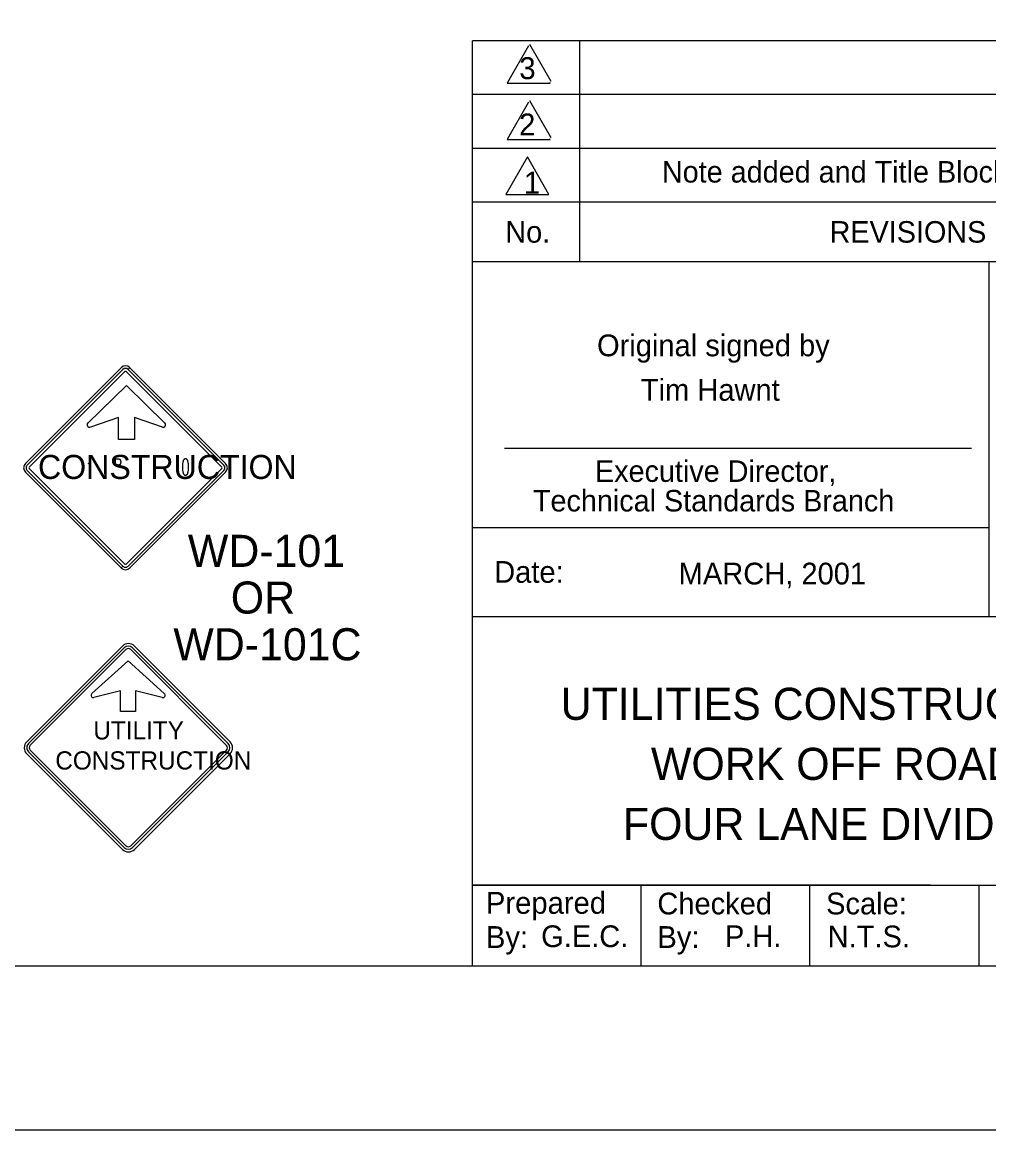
# Model space of a CAD drawing. Extents: x 1351 to 1567, y 178 to 457.
# Drawn here: x 1454.7 to 1518.5, y 177.9 to 251 of the extents above; entities that cross this region are included whole.
import ezdxf

# ---------------------------------------------------------------- set-up
doc = ezdxf.new("R2010")
doc.units = 0
for name, color, linetype in [('Level 1', 7, 'Continuous'), ('Level 10', 7, 'Continuous'), ('Level 60', 7, 'Continuous')]:
    doc.layers.add(name, color=color, linetype=linetype)

msp = doc.modelspace()

# ---------------------------------------------------------------- linework, layer by layer
at = {"layer": 'Level 1'}
for p, q in [((1454.953, 221.873), (1461.263, 228.183)), ((1455.068, 221.758), (1461.378, 228.068)), ((1455.206, 221.62), (1461.516, 227.93)), ((1461.594, 227.93), (1467.905, 221.62)), ((1461.847, 228.183), (1461.732, 228.068)), ((1461.732, 228.068), (1468.042, 221.758)), ((1461.732, 228.068), (1461.732, 228.068)), ((1461.847, 228.183), (1468.157, 221.873)), ((1459.07, 224.537), (1461.611, 227.012)), ((1461.612, 227.012), (1464.153, 224.537)), ((1461.085, 224.907), (1459.236, 224.268)), ((1461.085, 223.45), (1461.085, 224.907)), ((1463.987, 224.268), (1462.138, 224.907)), ((1462.138, 224.907), (1462.138, 223.45)), ((1462.138, 223.45), (1461.085, 223.45)), ((1461.114, 222.145), (1461.125, 222.145)), ((1461.114, 222.145), (1461.125, 222.145)), ((1461.378, 215.094), (1455.068, 221.404)), ((1461.516, 215.232), (1455.206, 221.542)), ((1467.905, 221.542), (1461.594, 215.232)), ((1468.042, 221.404), (1461.732, 215.094)), ((1461.263, 214.979), (1454.953, 221.289)), ((1468.157, 221.289), (1461.847, 214.979)), ((1461.378, 215.094), (1461.263, 214.979)), ((1461.263, 214.98), (1461.263, 214.979)), ((1461.378, 215.095), (1461.378, 215.094)), ((1461.531, 215.247), (1461.516, 215.232)), ((1459.47, 206.433), (1459.47, 206.433)), ((1459.47, 206.433), (1459.47, 206.433)), ((1459.47, 206.433), (1459.47, 206.433))]:
    msp.add_line(p, q, dxfattribs=at)
for points in [[(1461.125, 222.145), (1460.878, 222.145), (1460.878, 221.785), (1461.125, 221.785)], [(1461.125, 222.145), (1460.878, 222.145), (1460.878, 221.785), (1461.125, 221.785)], [(1461.114, 221.785), (1461.125, 221.785), (1461.137, 221.796), (1461.148, 221.796), (1461.159, 221.796), (1461.171, 221.796), (1461.171, 221.807), (1461.182, 221.807), (1461.193, 221.807), (1461.204, 221.819), (1461.216, 221.83), (1461.227, 221.841), (1461.238, 221.852), (1461.238, 221.864), (1461.238, 221.875), (1461.249, 221.897), (1461.249, 221.909), (1461.249, 221.92), (1461.249, 221.942), (1461.261, 221.954), (1461.261, 221.965), (1461.261, 221.987), (1461.249, 221.999), (1461.249, 222.01), (1461.249, 222.032), (1461.249, 222.044), (1461.238, 222.055), (1461.238, 222.078), (1461.227, 222.089), (1461.227, 222.1), (1461.216, 222.111), (1461.204, 222.111), (1461.204, 222.123), (1461.193, 222.123), (1461.182, 222.134), (1461.171, 222.134), (1461.159, 222.134), (1461.148, 222.145), (1461.137, 222.145), (1461.125, 222.145), (1461.114, 222.145)], [(1461.114, 221.785), (1461.125, 221.785), (1461.137, 221.796), (1461.148, 221.796), (1461.159, 221.796), (1461.171, 221.796), (1461.171, 221.807), (1461.182, 221.807), (1461.193, 221.807), (1461.204, 221.819), (1461.216, 221.83), (1461.227, 221.841), (1461.238, 221.852), (1461.238, 221.864), (1461.238, 221.875), (1461.249, 221.897), (1461.249, 221.909), (1461.249, 221.92), (1461.249, 221.942), (1461.261, 221.954), (1461.261, 221.965), (1461.261, 221.987), (1461.249, 221.999), (1461.249, 222.01), (1461.249, 222.032), (1461.249, 222.044), (1461.238, 222.055), (1461.238, 222.078), (1461.227, 222.089), (1461.227, 222.1), (1461.216, 222.111), (1461.204, 222.111), (1461.204, 222.123), (1461.193, 222.123), (1461.182, 222.134), (1461.171, 222.134), (1461.159, 222.134), (1461.148, 222.145), (1461.137, 222.145), (1461.125, 222.145), (1461.114, 222.145)], [(1465.36, 221.199), (1465.371, 221.188), (1465.371, 221.177), (1465.382, 221.165), (1465.394, 221.154), (1465.394, 221.143), (1465.405, 221.132), (1465.416, 221.132), (1465.427, 221.12), (1465.439, 221.12), (1465.439, 221.109), (1465.45, 221.109), (1465.461, 221.109), (1465.473, 221.098), (1465.484, 221.098), (1465.495, 221.098), (1465.506, 221.098), (1465.518, 221.098), (1465.529, 221.098), (1465.54, 221.098), (1465.551, 221.098), (1465.563, 221.109), (1465.574, 221.109), (1465.585, 221.109), (1465.596, 221.12), (1465.608, 221.132), (1465.619, 221.143), (1465.63, 221.143), (1465.63, 221.154), (1465.641, 221.165), (1465.653, 221.177), (1465.664, 221.188), (1465.664, 221.199), (1465.675, 221.233), (1465.675, 221.267), (1465.686, 221.301), (1465.698, 221.334), (1465.698, 221.368), (1465.709, 221.402), (1465.709, 221.447), (1465.72, 221.481), (1465.72, 221.515), (1465.72, 221.548), (1465.72, 221.582), (1465.72, 221.616), (1465.72, 221.65), (1465.72, 221.683), (1465.72, 221.717), (1465.72, 221.751), (1465.709, 221.796), (1465.709, 221.83), (1465.709, 221.864), (1465.698, 221.897), (1465.698, 221.931), (1465.686, 221.965), (1465.675, 221.999), (1465.675, 222.032), (1465.664, 222.066), (1465.653, 222.078), (1465.653, 222.089), (1465.641, 222.1), (1465.63, 222.111), (1465.63, 222.123), (1465.619, 222.134), (1465.608, 222.134), (1465.596, 222.145), (1465.585, 222.156), (1465.574, 222.156), (1465.563, 222.156), (1465.551, 222.168), (1465.54, 222.168), (1465.529, 222.168), (1465.518, 222.168), (1465.506, 222.168), (1465.495, 222.168), (1465.484, 222.168), (1465.473, 222.168), (1465.461, 222.168), (1465.45, 222.156), (1465.439, 222.156), (1465.439, 222.145), (1465.427, 222.145), (1465.416, 222.134), (1465.405, 222.134), (1465.405, 222.123), (1465.394, 222.111), (1465.382, 222.111), (1465.382, 222.1), (1465.371, 222.089), (1465.371, 222.078), (1465.36, 222.066), (1465.36, 222.055), (1465.36, 222.044), (1465.36, 222.032), (1465.349, 221.999), (1465.337, 221.976), (1465.337, 221.942), (1465.326, 221.909), (1465.315, 221.875), (1465.315, 221.841), (1465.315, 221.807)], [(1465.36, 221.199), (1465.371, 221.188), (1465.371, 221.177), (1465.382, 221.165), (1465.394, 221.154), (1465.394, 221.143), (1465.405, 221.132), (1465.416, 221.132), (1465.427, 221.12), (1465.439, 221.12), (1465.439, 221.109), (1465.45, 221.109), (1465.461, 221.109), (1465.473, 221.098), (1465.484, 221.098), (1465.495, 221.098), (1465.506, 221.098), (1465.518, 221.098), (1465.529, 221.098), (1465.54, 221.098), (1465.551, 221.098), (1465.563, 221.109), (1465.574, 221.109), (1465.585, 221.109), (1465.596, 221.12), (1465.608, 221.132), (1465.619, 221.143), (1465.63, 221.143), (1465.63, 221.154), (1465.641, 221.165), (1465.653, 221.177), (1465.664, 221.188), (1465.664, 221.199), (1465.675, 221.233), (1465.675, 221.267), (1465.686, 221.301), (1465.698, 221.334), (1465.698, 221.368), (1465.709, 221.402), (1465.709, 221.447), (1465.72, 221.481), (1465.72, 221.515), (1465.72, 221.548), (1465.72, 221.582), (1465.72, 221.616), (1465.72, 221.65), (1465.72, 221.683), (1465.72, 221.717), (1465.72, 221.751), (1465.709, 221.796), (1465.709, 221.83), (1465.709, 221.864), (1465.698, 221.897), (1465.698, 221.931), (1465.686, 221.965), (1465.675, 221.999), (1465.675, 222.032), (1465.664, 222.066), (1465.653, 222.078), (1465.653, 222.089), (1465.641, 222.1), (1465.63, 222.111), (1465.63, 222.123), (1465.619, 222.134), (1465.608, 222.134), (1465.596, 222.145), (1465.585, 222.156), (1465.574, 222.156), (1465.563, 222.156), (1465.551, 222.168), (1465.54, 222.168), (1465.529, 222.168), (1465.518, 222.168), (1465.506, 222.168), (1465.495, 222.168), (1465.484, 222.168), (1465.473, 222.168), (1465.461, 222.168), (1465.45, 222.156), (1465.439, 222.156), (1465.439, 222.145), (1465.427, 222.145), (1465.416, 222.134), (1465.405, 222.134), (1465.405, 222.123), (1465.394, 222.111), (1465.382, 222.111), (1465.382, 222.1), (1465.371, 222.089), (1465.371, 222.078), (1465.36, 222.066), (1465.36, 222.055), (1465.36, 222.044), (1465.36, 222.032), (1465.349, 221.999), (1465.337, 221.976), (1465.337, 221.942), (1465.326, 221.909), (1465.315, 221.875), (1465.315, 221.841), (1465.315, 221.807)], [(1459.245, 221.785), (1459.087, 221.875)], [(1465.315, 221.807), (1465.304, 221.774), (1465.304, 221.74), (1465.304, 221.706), (1465.304, 221.672), (1465.304, 221.638), (1465.304, 221.605), (1465.304, 221.571), (1465.304, 221.537), (1465.304, 221.503), (1465.315, 221.469), (1465.315, 221.436), (1465.315, 221.402), (1465.326, 221.368), (1465.326, 221.334), (1465.337, 221.301), (1465.349, 221.267), (1465.349, 221.233), (1465.36, 221.199)], [(1465.315, 221.807), (1465.304, 221.774), (1465.304, 221.74), (1465.304, 221.706), (1465.304, 221.672), (1465.304, 221.638), (1465.304, 221.605), (1465.304, 221.571), (1465.304, 221.537), (1465.304, 221.503), (1465.315, 221.469), (1465.315, 221.436), (1465.315, 221.402), (1465.326, 221.368), (1465.326, 221.334), (1465.337, 221.301), (1465.349, 221.267), (1465.349, 221.233), (1465.36, 221.199)], [(1455.04, 203.519), (1461.351, 209.829)], [(1455.158, 203.401), (1461.469, 209.711)], [(1462.02, 209.711), (1468.332, 203.398)], [(1462.139, 209.828), (1468.451, 203.516)], [(1455.277, 203.282), (1461.588, 209.592)], [(1461.903, 209.592), (1468.214, 203.279)], [(1459.336, 206.688), (1461.724, 208.862), (1464.115, 206.688)], [(1459.336, 206.688), (1461.724, 208.862), (1464.115, 206.688)], [(1459.336, 206.688), (1461.724, 208.862), (1464.115, 206.688)], [(1463.977, 206.433), (1462.221, 206.885), (1462.221, 205.516), (1461.232, 205.516), (1461.232, 206.885), (1459.47, 206.433)], [(1463.977, 206.433), (1462.221, 206.885), (1462.221, 205.516), (1461.232, 205.516), (1461.232, 206.885), (1459.47, 206.433)], [(1463.977, 206.433), (1462.221, 206.885), (1462.221, 205.516), (1461.232, 205.516), (1461.232, 206.885), (1459.47, 206.433)], [(1461.351, 196.418), (1455.04, 202.729)], [(1461.469, 196.537), (1455.158, 202.848)], [(1461.588, 196.654), (1455.277, 202.966)], [(1468.214, 202.964), (1461.903, 196.654)], [(1468.332, 202.846), (1462.021, 196.537)], [(1468.451, 202.728), (1462.139, 196.418)]]:
    msp.add_lwpolyline(points, dxfattribs=at)
for centre, radius, start, end in [((1461.555, 227.892), 0.413, 45.00012, 135), ((1461.555, 227.892), 0.25, 45.00012, 135), ((1461.555, 227.892), 0.0552, 44.99999, 135), ((1459.183, 224.422), 0.162, 134.244, 289.06341), ((1464.04, 224.422), 0.162, 250.93659, 45.756), ((1455.245, 221.581), 0.413, 135, 225), ((1455.245, 221.581), 0.25, 135, 225.00066), ((1455.245, 221.581), 0.0552, 135, 225), ((1467.865, 221.581), 0.0552, 315.00001, 44.99827), ((1467.865, 221.581), 0.25, 315, 45), ((1467.865, 221.581), 0.413, 315, 45), ((1461.555, 215.271), 0.413, 225, 315), ((1461.555, 215.271), 0.25, 224.99953, 315.00034), ((1461.555, 215.271), 0.0553, 225, 315.00069), ((1461.745, 209.433), 0.558, 44.99496, 134.99496), ((1461.745, 209.433), 0.558, 44.99496, 134.99496), ((1461.745, 209.433), 0.39, 44.99496, 134.99496), ((1461.745, 209.433), 0.223, 44.99496, 134.99496), ((1459.437, 206.577), 0.15, 132.30479, 284.40748), ((1459.437, 206.577), 0.15, 132.30479, 284.40748), ((1459.437, 206.577), 0.15, 132.30479, 284.40748), ((1464.015, 206.577), 0.15, 255.59252, 47.69521), ((1464.015, 206.577), 0.15, 255.59252, 47.69521), ((1464.015, 206.577), 0.15, 255.59252, 47.69521), ((1455.435, 203.124), 0.558, 134.99495, 224.99495), ((1455.435, 203.124), 0.39, 134.99495, 224.99495), ((1455.435, 203.124), 0.223, 134.99495, 224.99495), ((1468.056, 203.121), 0.223, 314.99496, 44.99495), ((1468.056, 203.121), 0.39, 314.99496, 44.99495), ((1468.056, 203.121), 0.558, 314.99496, 44.99495), ((1461.746, 196.812), 0.39, 224.99496, 314.99495), ((1461.746, 196.812), 0.223, 224.99496, 314.99495), ((1461.746, 196.812), 0.558, 224.99496, 314.99495)]:
    msp.add_arc(centre, radius, start, end, dxfattribs=at)
at = {"layer": 'Level 60'}
for p, q in [((1548.312, 249.746), (1484.432, 249.746)), ((1548.312, 249.746), (1484.432, 249.746)), ((1484.439, 243.274), (1484.439, 249.746)), ((1484.439, 243.274), (1484.439, 249.746)), ((1491.529, 243.274), (1491.529, 249.746)), ((1491.529, 243.274), (1491.529, 249.746)), ((1548.312, 246.197), (1484.432, 246.197)), ((1548.312, 246.197), (1484.432, 246.197)), ((1484.439, 235.196), (1484.439, 243.274)), ((1484.439, 235.196), (1484.439, 243.274)), ((1491.529, 235.196), (1491.529, 243.274)), ((1491.529, 235.196), (1491.529, 243.274)), ((1548.312, 242.648), (1484.432, 242.648)), ((1548.312, 242.648), (1484.432, 242.648)), ((1548.312, 239.1), (1484.432, 239.1)), ((1548.312, 239.1), (1484.432, 239.1)), ((1484.439, 188.732), (1484.439, 235.196)), ((1484.439, 235.196), (1548.312, 235.196)), ((1484.439, 235.196), (1548.312, 235.196)), ((1518.489, 235.196), (1518.489, 211.787)), ((1518.489, 235.196), (1518.489, 235.196)), ((1486.547, 222.882), (1517.348, 222.882)), ((1484.439, 217.639), (1518.489, 217.639)), ((1484.439, 211.787), (1548.282, 211.787)), ((1484.439, 194.053), (1548.282, 194.053)), ((1514.639, 194.053), (1484.439, 194.053)), ((1495.57, 188.732), (1495.57, 194.053)), ((1506.7, 188.732), (1506.7, 194.053)), ((1517.829, 194.053), (1517.829, 188.732)), ((1499.902, 188.732), (1499.902, 188.732))]:
    msp.add_line(p, q, dxfattribs=at)
for points in [[(1567.408, 456.923), (1351.408, 456.923), (1351.408, 177.923), (1567.408, 177.923)], [(1548.282, 446.114), (1361.408, 446.114), (1361.408, 188.732), (1548.282, 188.732)], [(1488.059, 242.081), (1486.64, 239.611), (1489.478, 239.611)], [(1488.059, 242.081), (1486.64, 239.611), (1489.478, 239.611)]]:
    msp.add_lwpolyline(points, close=True, dxfattribs=at)
for points in [[(1488.138, 249.415), (1486.745, 246.99)], [(1488.138, 249.415), (1486.745, 246.99)], [(1489.62, 247.067), (1488.226, 249.492)], [(1489.62, 247.067), (1488.226, 249.492)], [(1486.745, 246.99), (1486.719, 246.945), (1489.558, 246.945), (1489.532, 246.99)], [(1486.745, 246.99), (1486.719, 246.945), (1489.558, 246.945), (1489.532, 246.99)], [(1488.138, 245.699), (1486.745, 243.274)], [(1488.138, 245.699), (1486.745, 243.274)], [(1489.62, 243.351), (1488.226, 245.776)], [(1489.62, 243.351), (1488.226, 245.776)], [(1486.745, 243.274), (1486.719, 243.229), (1489.558, 243.229), (1489.532, 243.274)], [(1486.745, 243.274), (1486.719, 243.229), (1489.558, 243.229), (1489.532, 243.274)]]:
    msp.add_lwpolyline(points, dxfattribs=at)

# ---------------------------------------------------------------- texts
at = {"layer": 'Level 1'}
for s, height, p in [('CONSTRUCTION', 1.584, (1455.785, 220.847)), ('UTILITY', 1.2, (1459.435, 203.667)), ('CONSTRUCTION', 1.2, (1456.926, 201.686))]:
    msp.add_text(s, height=height, dxfattribs=at).set_placement(p)
at = {"layer": 'Level 10'}
for s, p in [('WD-101', (1465.668, 215.048)), ('OR', (1468.499, 211.968)), ('WD-101C', (1464.709, 208.888))]:
    msp.add_text(s, height=2.1151, rotation=360, dxfattribs=at).set_placement(p)
at = {"layer": 'Level 60'}
for s, height, rotation, p in [('3', 1.448, 360, (1487.528, 247.214)), ('3', 1.448, 360, (1487.528, 247.214)), ('2', 1.448, 360, (1487.511, 243.498)), ('2', 1.448, 360, (1487.511, 243.498)), ('1', 1.448, 360, (1487.832, 239.668)), ('1', 1.448, 360, (1487.832, 239.668)), ('No.', 1.4194, 360, (1486.611, 236.431)), ('No.', 1.4194, 360, (1486.611, 236.431)), ('REVISIONS', 1.4194, 360, (1507.994, 236.431)), ('REVISIONS', 1.4194, 360, (1507.994, 236.431)), ('Date:', 1.4329, 360, (1485.873, 214.001)), ('UTILITIES CONSTRUCTION - SIGNING', 2.115, 359.99999, (1490.256, 204.961)), ('WORK OFF ROAD SURFACE', 2.115, 359.99999, (1496.21, 201.002)), ('FOUR LANE DIVIDED HIGHWAY', 2.115, 359.99999, (1494.361, 197.042)), ('Prepared', 1.44, 360, (1485.327, 192.173)), ('Checked', 1.4329, 360, (1496.633, 192.131)), ('Scale:', 1.4329, 360, (1507.763, 192.131)), ('G.E.C.', 1.433, 360, (1488.97, 189.974)), ('P.H.', 1.433, 360, (1501.092, 189.974)), ('    N.T.S.   ', 1.43292, 360, (1505.734, 189.96)), ('By:', 1.44, 360, (1485.327, 189.917)), ('By:', 1.44, 360, (1496.633, 189.917))]:
    msp.add_text(s, height=height, rotation=rotation, dxfattribs=at).set_placement(p)
for s, height, p in [('Note added and Title Block updated.', 1.419, (1496.933, 240.394)), ('Original signed by', 1.434, (1492.654, 228.939)), ('Tim Hawnt', 1.434, (1495.544, 226.005)), ('Executive Director,', 1.41872, (1492.521, 220.654)), ('Technical Standards Branch', 1.41872, (1488.427, 218.703)), ('MARCH, 2001', 1.434, (1498.039, 213.89))]:
    msp.add_text(s, height=height, dxfattribs=at).set_placement(p)

doc.saveas('drawing.dxf')
